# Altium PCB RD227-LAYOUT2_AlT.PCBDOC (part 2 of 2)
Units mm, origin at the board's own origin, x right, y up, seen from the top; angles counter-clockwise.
Board outline 90 x 40 mm, 4 copper layers (TOP, Mid-Layer 1, Mid-Layer 2, BOTTOM), stack 0.711 mm thick; 157 components, 70 nets, 396 pads, 438 vias.
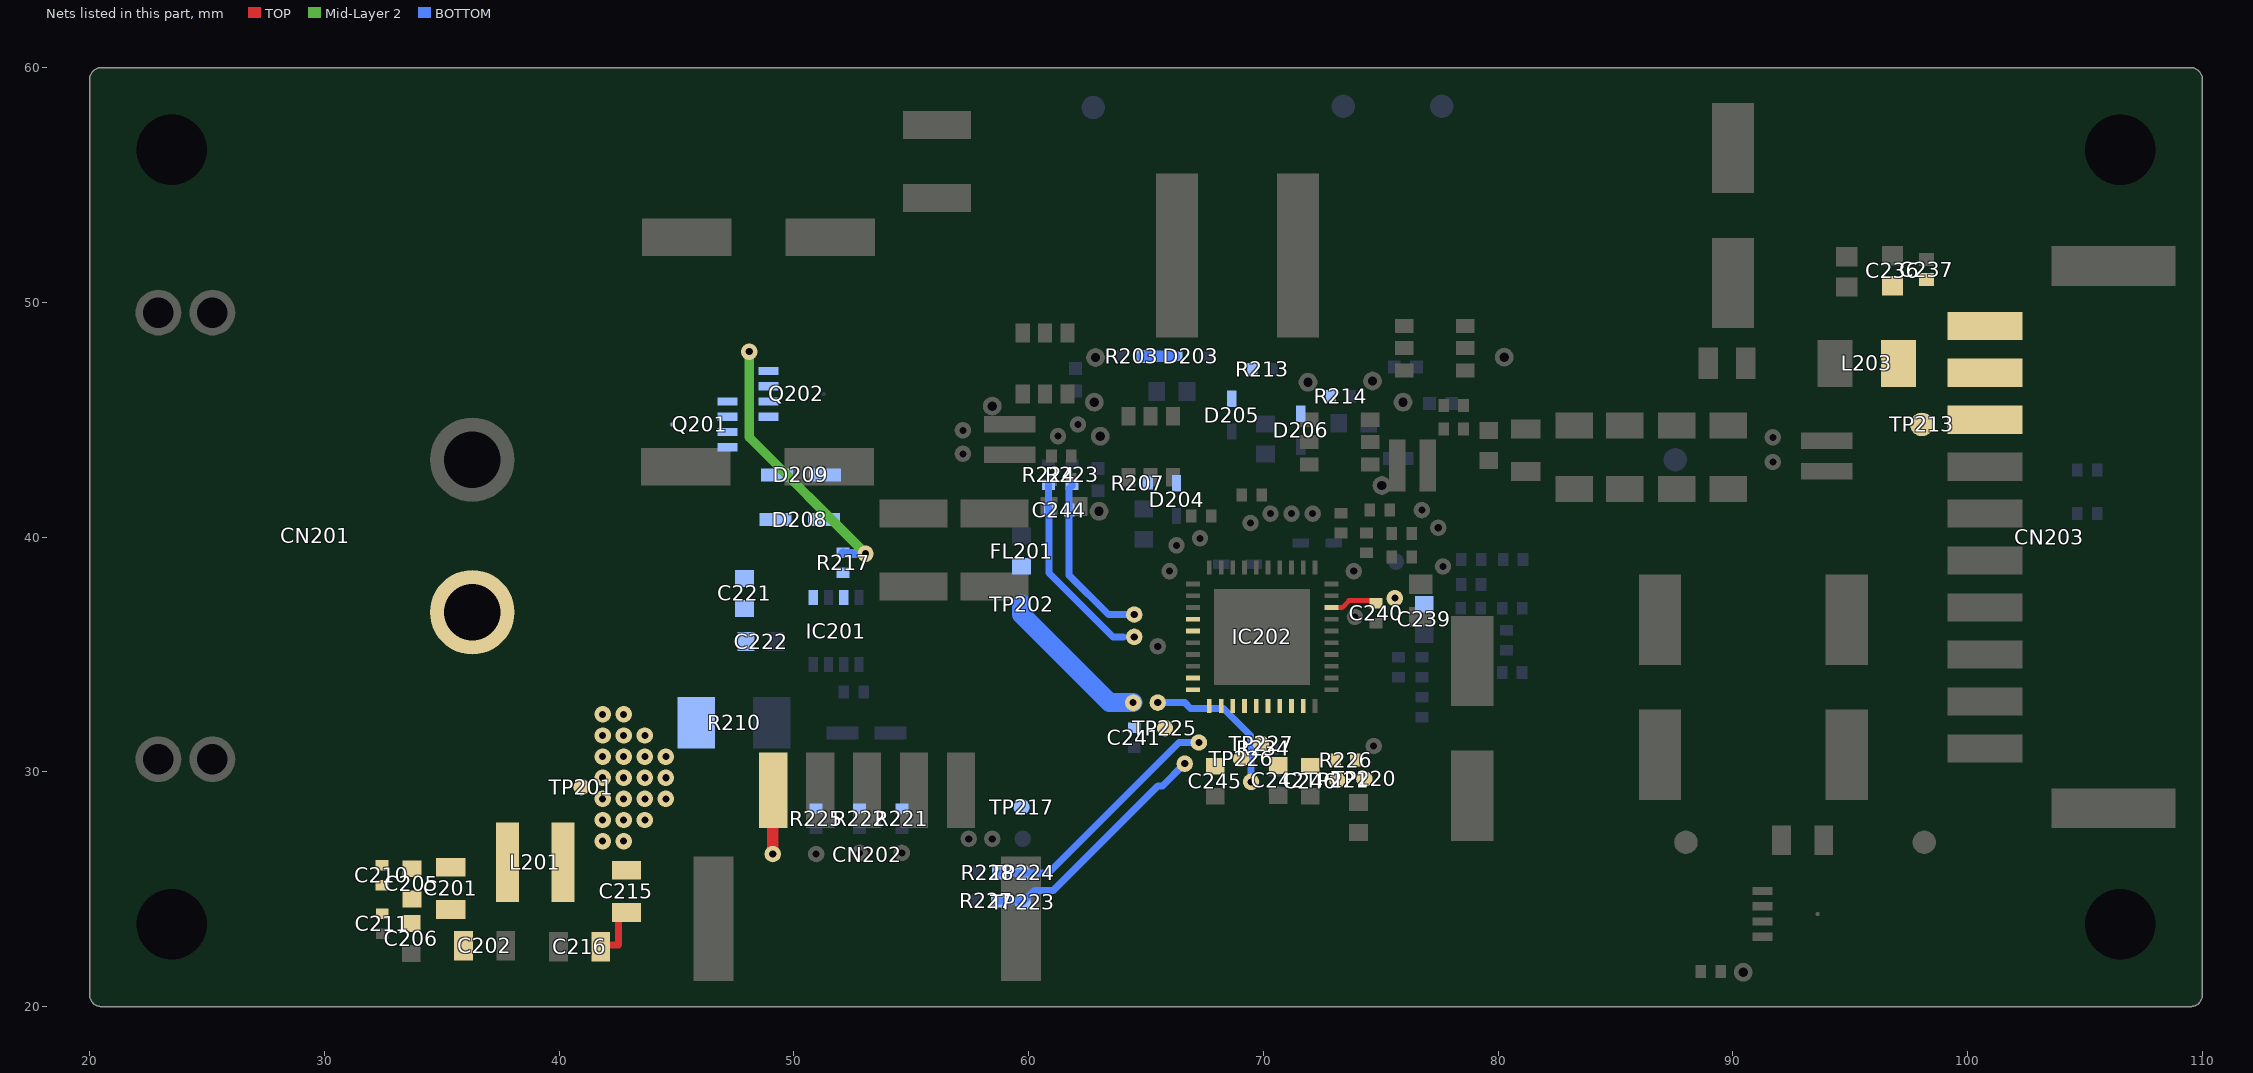
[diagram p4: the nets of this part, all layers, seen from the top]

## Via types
v1: diameter 0.7, hole 0.3, TOP to BOTTOM, 412 vias
v2: diameter 0.8, hole 0.4, TOP to BOTTOM, 26 vias

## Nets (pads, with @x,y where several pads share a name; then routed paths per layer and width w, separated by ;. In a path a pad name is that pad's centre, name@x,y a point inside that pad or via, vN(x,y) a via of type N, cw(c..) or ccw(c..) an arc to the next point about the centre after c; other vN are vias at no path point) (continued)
SIG335: C244.1 IC202.5 pad.@64.5,35.75 R224.1 | length 8.5
  BOTTOM w0.2: 64.05,35.75 pad.@64.5,35.75
  BOTTOM w0.3: R224.1@60.85,42.225 60.85,41.175 C244.1@60.875,41.15 60.875,38.475 63.6,35.75 64.05,35.75
SIG337: C244.2 IC202.4 pad.@64.5,36.7 R223.1 | length 7.4
  BOTTOM w0.3: R223.1@61.85,42.225 61.84,42.235 61.84,42.18 61.725,42.065 C244.2@61.725,41.15 61.725,38.375 63.4,36.7 pad.@64.5,36.7
SIG341: IC202.10 TP225.1
SIG344: IC202.19 R226.1 TP220.1
SIG345: IC202.18 R226.2 TP221.1
SIG346: C245.1 IC202.13
SIG347: C246.1 IC202.17
SIG349: IC202.14 TP226.1
SIG350: IC202.15 TP227.1
SIG369: IC202.11 pad.@66.65,30.35 R227.1 TP223.1 | length 10.4
  BOTTOM w0.3: R227.1@58.675,24.5 59.7,24.5 TP223.1@59.75,24.45 60.25,24.95 61.05,24.95 65.503,29.403 65.703,29.403 pad.@66.65,30.35
SIG370: IC202.12 pad.@67.25,31.25 R228.1 TP224.1 | length 10.9
  BOTTOM w0.3: R228.1@58.675,25.7 TP224.1@59.75,25.7 60.85,25.7 66.4,31.25 pad.@67.25,31.25
SIG395: C201.1 C202.2
SIG396: C205.1 C206.2
SIG397: C210.1 C211.2
SIG411: C215.1 C216.2 | length 2.1
  TOP w0.3: C216.2@41.802,22.63 42.531,22.63 C215.1@42.531,23.955
SIG422: D203.A R203.2 | length 1.3
  BOTTOM w0.5: R203.2@64.875,47.7 D203.A@66.2,47.7
SIG423: D204.A R207.2
SIG424: C221.1 C222.2
SIG425: D205.A R213.2
SIG426: D206.A R214.2
SIG433: IC201.3 R217.1
SIG436: D209.A Q201.1 Q201.2 Q201.3 Q202.1 Q202.2 Q202.3
SIG437: D208.C D209.C
SIG438: D208.A Q201.4 Q202.4 R217.2 | length 11.6
  Mid-Layer 2 w0.4: v1(48.1,47.9) 48.1,44.25 v1(53.05,39.3)
  BOTTOM w0.4: R217.2@52.1,39.325 52.125,39.3 v1(53.05,39.3) v1@53.075,39.3
VBAT: C239.2 C240.2 FL201.2 IC202.28 TP202.1 | length 9
  TOP w0.2: IC202.28@72.898,37 73.35,37 73.65,37.3 C240.2@74.925,37.3
  BOTTOM w0.3: v1(75.6,37.4) v1@75.646,37.446
  BOTTOM w0.8: TP202.1@59.7,37.15 59.7,36.7 63.45,32.95 v1(64.45,32.95)
VBUS: C236.2 C237.2 CN203.8 CN203.9 CN203.10 L203.2 TP213.1
VDD: C241.2 C242.1 CN202.1 IC202.9 IC202.16 pad.@49.1,26.5 pad.@65.5,32.95 pad.@69.475,29.575 R221.1 R222.1 R225.1 R234.1 TP217.1 | length 9.3
  TOP w0.5: pad.@49.1,26.5 CN202.1@49.1,29.2
  BOTTOM w0.3: pad.@65.5,32.95 66.65,32.95 66.9,32.7 68.3,32.7 69.45,31.55 69.45,31.125 R234.1@69.575,31 69.475,30.9 pad.@69.475,29.575
VIN: C201.2 C205.2 C210.2 CN201.1 L201.1
VIN2: C215.2 C221.2 IC201.1 L201.2 Q201.5 R210.2 TP201.1
  other v1: 41.85,27.05 42.75,27.05 41.85,27.95 42.75,27.95 43.65,27.95 41.85,28.85 42.75,28.85 43.65,28.85 44.55,28.85 41.85,29.75 42.75,29.75 43.65,29.75 44.55,29.75 41.85,30.65 42.75,30.65 43.65,30.65 44.55,30.65 41.85,31.55 42.75,31.55 43.65,31.55 41.85,32.45 42.75,32.45
pads on no net: CAM10. CAM11. CAM12. CAM13. IC201.4 IC201.7 IC201.8

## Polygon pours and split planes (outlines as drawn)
CSN2 on TOP "TOP65" (solid, pour order 134): 21 vertices, not listed, extent 89.1,43.8 95.3,52.7
VBUS on TOP "TOP64" (solid, pour order 133): 20 vertices, not listed, extent 96.35,44.221 102.3,51
SHLD_SNS on TOP "TOP63" (solid, pour order 132): 54 vertices, not listed, extent 92.142,20.987 108.927,52.721
CSP2 on TOP "TOP62" (solid, pour order 131): 71.7,41.75 cw(c71.7,41.9) 71.55,41.9 71.55,44.2 cw(c71.7,44.2) 71.7,44.35 75.838,44.35 cw(c75.838,44.2) 75.944,44.306 76.063,44.187 cw(c75.957,44.081) 76.107,44.081 76.107,42.25 cw(c75.957,42.25) 75.957,42.1 75.6,42.1 75.294,41.794 cw(c75.188,41.9) 75.188,41.75
LX2 on TOP "TOP61" (solid, pour order 130): 22 vertices, not listed, extent 70.6,44.7 79,56.35
LX1 on TOP "TOP60" (solid, pour order 129): 25 vertices, not listed, extent 61.35,41.9 67.3,56.45
GND_P on TOP "TOP59" (solid, pour order 128): 215 vertices, not listed, extent 21.05,21 95.65,58.93
DH1_Q on TOP "TOP58" (solid, pour order 127): 62.571,45.4 cw(c62.571,45.45) 62.535,45.415 62.25,45.7 61.65,45.7 cw(c61.65,45.75) 61.6,45.75 61.6,46.45 cw(c61.65,46.45) 61.65,46.5 62.429,46.5 cw(c62.429,46.45) 62.465,46.485 62.835,46.115 cw(c62.8,46.079) 62.85,46.079 62.85,45.45 cw(c62.8,45.45) 62.8,45.4
DL1_Q on TOP "TOP57" (solid, pour order 126): 62.871,44 cw(c62.871,44.05) 62.835,44.015 62.765,44.085 cw(c62.8,44.121) 62.75,44.121 62.75,44.479 cw(c62.8,44.479) 62.765,44.515 63.785,45.535 cw(c63.821,45.5) 63.821,45.55 64.25,45.55 cw(c64.25,45.5) 64.3,45.5 64.3,44.8 cw(c64.25,44.8) 64.25,44.75 64,44.75 63.265,44.015 cw(c63.229,44.05) 63.229,44
DL2_Q on TOP "TOP56" (solid, pour order 125): 75.65,45.7 cw(c75.65,45.75) 75.6,45.75 75.6,47.1 cw(c75.65,47.1) 75.65,47.15 76.35,47.15 cw(c76.35,47.1) 76.4,47.1 76.4,45.871 cw(c76.35,45.871) 76.385,45.835 76.265,45.715 cw(c76.229,45.75) 76.229,45.7
DH2_Q on TOP "TOP55" (solid, pour order 124): 74.2,45.05 cw(c74.2,45.1) 74.15,45.1 74.15,45.929 cw(c74.2,45.929) 74.165,45.965 74.3,46.1 74.3,46.65 cw(c74.35,46.65) 74.35,46.7 74.9,46.7 cw(c74.9,46.65) 74.95,46.65 74.95,45.1 cw(c74.9,45.1) 74.9,45.05
LX2 on TOP "TOP54" (solid, pour order 123): 19 vertices, not listed, extent 68.6,38.4 69.525,43.186
GND_P on TOP "TOP53" (solid, pour order 122): 35 vertices, not listed, extent 78.4,44.2 99.05,59
GND_A on TOP "TOP52" (solid, pour order 121): 77 vertices, not listed, extent 67.55,28.337 77.188,37
SIG344 on TOP "TOP51" (solid, pour order 120): 27 vertices, not listed, extent 71.6,29.7 74.55,33.152
SIG345 on TOP "TOP50" (solid, pour order 119): 20 vertices, not listed, extent 71.1,29.65 73.5,33.152
GDRV on TOP "TOP49" (solid, pour order 118): 89.3,21.1 cw(c89.3,21.15) 89.25,21.15 89.25,21.75 cw(c89.3,21.75) 89.3,21.8 90.2,21.8 90.837,22.437 90.837,23.05 cw(c90.887,23.05) 90.887,23.1 91.65,23.1 cw(c91.65,23.05) 91.7,23.05 91.7,21.721 cw(c91.65,21.721) 91.685,21.685 91.115,21.115 cw(c91.079,21.15) 91.079,21.1
CSP1 on TOP "TOP48" (solid, pour order 117): 23 vertices, not listed, extent 49.65,40.402 61.2,55.1
ADDR on TOP "TOP47" (solid, pour order 116): 70.6,39.2 cw(c70.7,39.2) 70.629,39.271 71.754,40.396 71.754,40.914 cw(c71.854,40.914) 71.854,41.014 72.327,41.014 cw(c72.327,40.914) 72.427,40.914 72.427,40.869 cw(c72.327,40.869) 72.398,40.798 72.2,40.6 cw(c72.1,40.6) 72.171,40.529 70.8,39.159 70.8,38.948 cw(c70.7,38.948) 70.6,38.948
BST2 on TOP "TOP46" (solid, pour order 115): 24 vertices, not listed, extent 69.6,38.8 70.65,41.95
SIG350 on TOP "TOP45" (solid, pour order 114): 69.65,31.2 cw(c69.65,31.3) 69.55,31.3 69.55,31.409 cw(c69.65,31.409) 69.579,31.479 69.6,31.5 69.6,33.052 cw(c69.7,33.052) 69.8,33.052 69.8,31.8 70.146,31.454 cw(c70.075,31.383) 70.175,31.383 70.175,31.316 cw(c70.075,31.316) 70.146,31.245 70.13,31.229 cw(c70.06,31.3) 70.06,31.2
VDD on TOP "TOP44" (solid, pour order 113): 24 vertices, not listed, extent 69.273,29.373 71,33.152
CSN1 on TOP "TOP43" (solid, pour order 112): 58.2,44.6 cw(c58.2,44.75) 58.05,44.75 58.05,48.9 cw(c58.2,48.9) 58.2,49.05 60.85,49.05 cw(c60.85,48.9) 61,48.9 61,46.162 cw(c60.85,46.162) 60.956,46.056 60.3,45.4 60.3,44.75 cw(c60.15,44.75) 60.15,44.6
GND_A on TOP "TOP42" (solid, pour order 111): 108.05,37.1 cw(c108.05,37.15) 108,37.15 108,43.8 cw(c108.05,43.8) 108.05,43.85 108.95,43.85 cw(c108.95,43.8) 109,43.8 109,37.15 cw(c108.95,37.15) 108.95,37.1
SIG397 on TOP "TOP41" (solid, pour order 110): 32.25,23.85 cw(c32.25,23.9) 32.2,23.9 32.2,25.2 cw(c32.25,25.2) 32.25,25.25 32.65,25.25 cw(c32.65,25.2) 32.7,25.2 32.7,23.9 cw(c32.65,23.9) 32.65,23.85
SIG396 on TOP "TOP40" (solid, pour order 109): 33.35,23.45 cw(c33.35,23.5) 33.3,23.5 33.3,24.55 cw(c33.35,24.55) 33.35,24.6 34.05,24.6 cw(c34.05,24.55) 34.1,24.55 34.1,23.5 cw(c34.05,23.5) 34.05,23.45
SIG395 on TOP "TOP39" (solid, pour order 108): 35.6,22 cw(c35.6,22.05) 35.55,22.05 35.55,22.4 34.815,23.135 cw(c34.85,23.171) 34.8,23.171 34.8,24.1 cw(c34.85,24.1) 34.85,24.15 35.95,24.15 cw(c35.95,24.1) 36,24.1 36,23.65 36.285,23.365 cw(c36.25,23.329) 36.3,23.329 36.3,22.05 cw(c36.25,22.05) 36.25,22
VIN2 on TOP "TOP38" (solid, pour order 107): 26 vertices, not listed, extent 39.666,24.507 44.9,33.454
SIG341 on TOP "TOP37" (solid, pour order 106): 24 vertices, not listed, extent 65.65,31.75 67.102,33.6
OUT on TOP "TOP36" (solid, pour order 105): 49 vertices, not listed, extent 76.694,32.75 96.1,45.85
VIN on TOP "TOP35" (solid, pour order 104): 41 vertices, not listed, extent 32.144,24.463 38.304,38.65
GND_A on TOP "TOP34" (solid, pour order 103): 46,21 cw(c46,21.15) 45.85,21.15 45.85,24.65 cw(c46,24.65) 46,24.8 55.45,24.8 56.55,25.9 56.55,30.85 cw(c56.7,30.85) 56.7,31 58.838,31 cw(c58.838,30.85) 58.944,30.956 60.506,29.394 cw(c60.4,29.288) 60.55,29.288 60.55,21.15 cw(c60.4,21.15) 60.4,21
CSN1 on TOP "TOP33" (solid, pour order 102): 61.821,44.65 cw(c61.821,44.7) 61.785,44.665 61.515,44.935 cw(c61.55,44.971) 61.5,44.971 61.5,45.05 cw(c61.55,45.05) 61.55,45.1 62.15,45.1 cw(c62.15,45.05) 62.2,45.05 62.2,44.7 cw(c62.15,44.7) 62.15,44.65
CSP1 on TOP "TOP32" (solid, pour order 101): 60.7,44 cw(c60.7,44.05) 60.65,44.05 60.65,44.179 cw(c60.7,44.179) 60.665,44.215 61.085,44.635 cw(c61.121,44.6) 61.121,44.65 61.25,44.65 cw(c61.25,44.6) 61.3,44.6 61.3,44.05 cw(c61.25,44.05) 61.25,44
LX1 on TOP "TOP31" (solid, pour order 100): 21 vertices, not listed, extent 67.25,38.4 68.3,43.2
ALERT on TOP "TOP30" (solid, pour order 99): 21 vertices, not listed, extent 72.1,31 74.8,32.841
SIG347 on TOP "TOP29" (solid, pour order 98): 71.7,29.9 cw(c71.7,30) 71.6,30 71.6,31.1 70.629,32.071 cw(c70.7,32.141) 70.6,32.141 70.6,33.052 cw(c70.7,33.052) 70.8,33.052 70.8,32.35 72.371,30.779 cw(c72.3,30.709) 72.4,30.709 72.4,30 cw(c72.3,30) 72.3,29.9
SIG349 on TOP "TOP28" (solid, pour order 97): 68.8,30.45 cw(c68.8,30.55) 68.7,30.55 68.7,31.009 cw(c68.8,31.009) 68.729,31.079 69.1,31.45 69.1,33.052 cw(c69.2,33.052) 69.3,33.052 69.3,30.9 69.371,30.829 cw(c69.3,30.759) 69.4,30.759 69.4,30.55 cw(c69.3,30.55) 69.3,30.45
SIG346 on TOP "TOP27" (solid, pour order 96): 67.65,29.9 cw(c67.65,30) 67.55,30 67.55,30.609 cw(c67.65,30.609) 67.579,30.679 67.85,30.95 67.85,31.388 cw(c68,31.388) 67.894,31.494 68.6,32.2 68.6,33.052 cw(c68.7,33.052) 68.8,33.052 68.8,31.591 cw(c68.7,31.591) 68.771,31.521 68.35,31.1 68.35,30 cw(c68.25,30) 68.25,29.9
SIG370 on TOP "TOP26" (solid, pour order 95): 67.129,31.15 cw(c67.129,31.25) 67.029,31.25 67.029,31.409 cw(c67.129,31.409) 67.059,31.479 67.224,31.644 cw(c67.294,31.574) 67.271,31.671 68.1,32.5 68.1,33.052 cw(c68.2,33.052) 68.3,33.052 68.3,32.391 cw(c68.2,32.391) 68.271,32.321 67.6,31.65 67.6,31.25 cw(c67.5,31.25) 67.5,31.15
SIG369 on TOP "TOP25" (solid, pour order 94): 19 vertices, not listed, extent 66.311,30.25 67.8,33.152
HVDP on TOP "TOP24" (solid, pour order 93): 74.45,31.95 cw(c74.45,32.05) 74.35,32.05 74.35,32.959 73.409,33.9 72.898,33.9 cw(c72.898,34) 72.898,34.1 73.45,34.1 cw(c73.45,34) 73.521,34.071 74.827,32.765 cw(c74.756,32.694) 74.856,32.694 74.856,32.452 74.967,32.079 cw(c74.871,32.05) 74.871,31.95
HVDM on TOP "TOP23" (solid, pour order 92): 73.441,32.75 cw(c73.441,32.85) 73.371,32.779 73.329,32.821 cw(c73.4,32.891) 73.3,32.891 73.3,33.259 73.159,33.4 72.898,33.4 cw(c72.898,33.5) 72.898,33.6 73.2,33.6 cw(c73.2,33.5) 73.271,33.571 73.92,32.921 73.921,32.921 cw(c73.85,32.85) 73.95,32.85 cw(c73.85,32.85) 73.85,32.75
HVCC2 on TOP "TOP22" (solid, pour order 91): 74.55,34.1 cw(c74.55,34.2) 74.479,34.129 73.709,34.9 72.898,34.9 cw(c72.898,35) 72.898,35.1 73.75,35.1 cw(c73.75,35) 73.821,35.071 74.342,34.549 cw(c74.35,34.5) 74.35,34.55 74.75,34.55 cw(c74.75,34.5) 74.8,34.5 74.8,34.3 cw(c74.8,34.2) 74.8,34.1
HVCC1 on TOP "TOP21" (solid, pour order 90): 18 vertices, not listed, extent 72.798,34.784 74.8,35.6
VDD on TOP "TOP20" (solid, pour order 89): 20 vertices, not listed, extent 65.3,32.6 67.102,34.1
GDRV on TOP "TOP19" (solid, pour order 88): 65.55,33.65 cw(c65.55,33.7) 65.5,33.7 65.5,34.3 cw(c65.55,34.3) 65.55,34.35 66.309,34.35 66.529,34.571 cw(c66.6,34.5) 66.6,34.6 67.002,34.6 cw(c67.002,34.5) 67.002,34.4 66.641,34.4 66.527,34.286 cw(c66.479,34.3) 66.515,34.265 66.514,34.264 65.915,33.665 cw(c65.879,33.7) 65.879,33.65
HVEN on TOP "TOP18" (solid, pour order 87): 65.45,35.05 cw(c65.45,35.1) 65.4,35.1 65.4,35.65 cw(c65.45,35.65) 65.45,35.7 65.779,35.7 cw(c65.779,35.65) 65.815,35.685 65.9,35.6 67.25,35.6 cw(c67.25,35.55) 67.3,35.55 67.3,35.45 cw(c67.25,35.45) 67.25,35.4 66.1,35.4 65.765,35.065 cw(c65.729,35.1) 65.729,35.05
SIG335 on TOP "TOP17" (solid, pour order 86): 64.25,35.7 cw(c64.25,35.75) 64.2,35.75 64.2,35.979 cw(c64.25,35.979) 64.215,36.015 64.285,36.085 cw(c64.321,36.05) 64.321,36.1 67.25,36.1 cw(c67.25,36.05) 67.3,36.05 67.3,35.95 cw(c67.25,35.95) 67.25,35.9 65,35.9 64.815,35.715 cw(c64.779,35.75) 64.779,35.7
SIG337 on TOP "TOP16" (solid, pour order 85): 64.55,36.4 cw(c64.55,36.45) 64.5,36.45 64.5,36.8 cw(c64.55,36.8) 64.55,36.85 64.729,36.85 cw(c64.729,36.8) 64.765,36.835 65,36.6 67.25,36.6 cw(c67.25,36.55) 67.3,36.55 67.3,36.45 cw(c67.25,36.45) 67.25,36.4
DL1 on TOP "TOP15" (solid, pour order 84): 66.521,37.4 cw(c66.521,37.45) 66.485,37.415 65.665,38.235 cw(c65.7,38.271) 65.65,38.271 65.65,38.5 cw(c65.7,38.5) 65.7,38.55 66.3,38.55 cw(c66.3,38.5) 66.35,38.5 66.35,37.95 66.7,37.6 67.2,37.6 cw(c67.2,37.55) 67.25,37.55 67.25,37.45 cw(c67.2,37.45) 67.2,37.4
BST1 on TOP "TOP14" (solid, pour order 83): 37 vertices, not listed, extent 65.95,37.9 67.2,40.85
DL2 on TOP "TOP13" (solid, pour order 82): 70.15,38.4 cw(c70.15,38.45) 70.1,38.45 70.1,39.529 cw(c70.15,39.529) 70.115,39.565 70.85,40.3 70.85,40.95 cw(c70.9,40.95) 70.9,41 71.5,41 cw(c71.5,40.95) 71.55,40.95 71.55,40.521 cw(c71.5,40.521) 71.535,40.485 70.3,39.25 70.3,38.45 cw(c70.25,38.45) 70.25,38.4
DH2 on TOP "TOP12" (solid, pour order 81): 69.15,38.45 cw(c69.15,38.5) 69.1,38.5 69.1,40.579 cw(c69.15,40.579) 69.115,40.615 69.235,40.735 cw(c69.271,40.7) 69.271,40.75 69.629,40.75 cw(c69.629,40.7) 69.665,40.735 69.785,40.615 cw(c69.75,40.579) 69.8,40.579 69.8,40.371 cw(c69.75,40.371) 69.785,40.335 69.3,39.85 69.3,38.5 cw(c69.25,38.5) 69.25,38.45
VBAT on TOP "TOP11" (solid, pour order 80): 74.621,36.95 cw(c74.621,37) 74.585,36.965 74.365,37.185 cw(c74.4,37.221) 74.35,37.221 74.35,37.35 cw(c74.4,37.35) 74.4,37.4 75.15,37.4 75.235,37.485 cw(c75.271,37.45) 75.271,37.5 75.85,37.5 cw(c75.85,37.45) 75.9,37.45 75.9,37.071 cw(c75.85,37.071) 75.885,37.035 75.815,36.965 cw(c75.779,37) 75.779,36.95
BIAS on TOP "TOP10" (solid, pour order 79): 20 vertices, not listed, extent 74.55,37.6 78,38.85
CSN2 on TOP "TOP9" (solid, pour order 78): 76.15,38.9 cw(c76.15,38.95) 76.1,38.95 76.1,39.4 cw(c76.15,39.4) 76.15,39.45 76.65,39.45 77.1,39.9 77.1,40.45 cw(c77.15,40.45) 77.15,40.5 77.75,40.5 cw(c77.75,40.45) 77.8,40.45 77.8,40.021 cw(c77.75,40.021) 77.785,39.985 76.715,38.915 cw(c76.679,38.95) 76.679,38.9
SIG328 on TOP "TOP8" (solid, pour order 77): 73,40.8 cw(c73,40.85) 72.95,40.85 72.95,41.2 cw(c73,41.2) 73,41.25 73.7,41.25 73.835,41.385 cw(c73.871,41.35) 73.871,41.4 74.6,41.4 cw(c74.6,41.35) 74.65,41.35 74.65,40.95 cw(c74.6,40.95) 74.6,40.9 74.2,40.9 74.115,40.815 cw(c74.079,40.85) 74.079,40.8
SIG324 on TOP "TOP7" (solid, pour order 76): 75.071,38.9 cw(c75.071,38.95) 75.035,38.915 74.85,39.1 74.2,39.1 cw(c74.2,39.15) 74.15,39.15 74.15,39.5 cw(c74.2,39.5) 74.2,39.55 75.079,39.55 cw(c75.079,39.5) 75.115,39.535 75.25,39.4 75.45,39.4 cw(c75.45,39.35) 75.5,39.35 75.5,38.95 cw(c75.45,38.95) 75.45,38.9
SIG310 on TOP "TOP6" (solid, pour order 75): 73.15,36.4 cw(c73.15,36.45) 73.1,36.45 73.1,36.55 cw(c73.15,36.55) 73.15,36.6 73.4,36.6 73.685,36.885 cw(c73.721,36.85) 73.721,36.9 73.9,36.9 cw(c73.9,36.85) 73.95,36.85 73.95,36.45 cw(c73.9,36.45) 73.9,36.4
SIG318 on TOP "TOP5" (solid, pour order 74): 72.75,37.9 cw(c72.75,37.95) 72.7,37.95 72.7,38.05 cw(c72.75,38.05) 72.75,38.1 73,38.1 73.435,38.535 cw(c73.471,38.5) 73.471,38.55 74,38.55 cw(c74,38.5) 74.05,38.5 74.05,38.25 cw(c74,38.25) 74,38.2 73.5,38.2 73.215,37.915 cw(c73.179,37.95) 73.179,37.9
OUT on TOP "TOP4" (solid, pour order 73): 76.15,39.95 cw(c76.15,40) 76.1,40 76.1,40.829 cw(c76.15,40.829) 76.115,40.865 76.385,41.135 cw(c76.421,41.1) 76.421,41.15 77,41.15 cw(c77,41.1) 77.05,41.1 77.05,41.021 cw(c77,41.021) 77.035,40.985 76.55,40.5 76.55,40 cw(c76.5,40) 76.5,39.95
CSP2 on TOP "TOP3" (solid, pour order 72): 75.3,40.9 cw(c75.3,40.95) 75.25,40.95 75.25,41.35 cw(c75.3,41.35) 75.3,41.4 75.65,41.4 75.885,41.635 cw(c75.921,41.6) 75.921,41.65 76.05,41.65 cw(c76.05,41.6) 76.1,41.6 76.1,41.371 cw(c76.05,41.371) 76.085,41.335 75.665,40.915 cw(c75.629,40.95) 75.629,40.9
SIG319 on TOP "TOP2" (solid, pour order 71): 75.271,39.85 cw(c75.271,39.9) 75.235,39.865 75.15,39.95 73.1,39.95 cw(c73.1,40) 73.05,40 73.05,40.35 cw(c73.1,40.35) 73.1,40.4 75.55,40.4 cw(c75.55,40.35) 75.6,40.35 75.6,39.9 cw(c75.55,39.9) 75.55,39.85
DH1 on TOP "TOP1" (solid, pour order 70): 67.65,38.4 cw(c67.65,38.45) 67.6,38.45 67.6,39.2 66.965,39.835 cw(c67,39.871) 66.95,39.871 66.95,40.079 cw(c67,40.079) 66.965,40.115 67.135,40.285 cw(c67.171,40.25) 67.171,40.3 67.429,40.3 cw(c67.429,40.25) 67.465,40.285 67.785,39.965 cw(c67.75,39.929) 67.8,39.929 67.8,38.45 cw(c67.75,38.45) 67.75,38.4
GND_P on Mid-Layer 1 "MID175" (solid, pour order 68): 138 vertices, not listed, extent 20.986,21 101.75,58.981
VIN2 on Mid-Layer 1 "MID168" (solid, pour order 61): 41.5,26.65 cw(c41.5,26.7) 41.45,26.7 41.45,32.85 cw(c41.5,32.85) 41.5,32.9 43.129,32.9 cw(c43.129,32.85) 43.165,32.885 44.935,31.115 cw(c44.9,31.079) 44.95,31.079 44.95,28.321 cw(c44.9,28.321) 44.935,28.285 43.315,26.665 cw(c43.279,26.7) 43.279,26.65
GND_A on Mid-Layer 1 "MID176" (solid, pour order 69): 29 vertices, not listed, extent 68.35,28.424 108.95,44.863
LX1 on Mid-Layer 1 "MID174" (solid, pour order 67): 63.8,43.05 cw(c63.8,43.2) 63.65,43.2 63.65,44.956 cw(c63.8,44.956) 63.8,45.106 66.4,45.106 cw(c66.4,44.956) 66.55,44.956 66.55,43.2 cw(c66.4,43.2) 66.4,43.05
SHLD_SNS on Mid-Layer 1 "MID173" (solid, pour order 66): 18 vertices, not listed, extent 92.2,20.987 106.598,33.739
CSP2 on Mid-Layer 1 "MID172" (solid, pour order 65): 71.9,41.85 cw(c71.9,42) 71.75,42 71.75,43.9 cw(c71.9,43.9) 71.9,44.05 74.15,44.05 cw(c74.15,43.9) 74.3,43.9 74.3,42 cw(c74.15,42) 74.15,41.85
CSN1 on Mid-Layer 1 "MID171" (solid, pour order 64): 59.05,46.5 cw(c59.05,46.65) 58.9,46.65 58.9,48.95 cw(c59.05,48.95) 59.05,49.1 60.9,49.1 cw(c60.9,48.95) 61.05,48.95 61.05,46.65 cw(c60.9,46.65) 60.9,46.5
VBAT on Mid-Layer 1 "MID170" (solid, pour order 63): 28 vertices, not listed, extent 64.05,31.855 75.879,37.523
CSP1 on Mid-Layer 1 "MID169" (solid, pour order 62): 54.271,44.15 cw(c54.271,44.2) 54.235,44.165 53.165,45.235 cw(c53.2,45.271) 53.15,45.271 53.15,50.35 cw(c53.2,50.35) 53.2,50.4 57.4,50.4 cw(c57.4,50.35) 57.45,50.35 57.45,46.171 cw(c57.4,46.171) 57.435,46.135 55.465,44.165 cw(c55.429,44.2) 55.429,44.15
SHLD_SNS on Mid-Layer 1 "MID167" (solid, pour order 60): 92.295,22.65 cw(c92.295,22.75) 92.195,22.75 92.195,24.668 cw(c92.295,24.668) 92.295,24.768 94.144,24.768 cw(c94.144,24.668) 94.244,24.668 94.244,22.75 cw(c94.144,22.75) 94.144,22.65
LX2 on Mid-Layer 1 "MID166" (solid, pour order 59): 76.4,46.95 cw(c76.4,47.1) 76.25,47.1 76.25,49.422 cw(c76.4,49.422) 76.4,49.572 78.1,49.572 cw(c78.1,49.422) 78.25,49.422 78.25,47.1 cw(c78.1,47.1) 78.1,46.95
GND_A on Mid-Layer 2 "MID287" (solid, pour order 58): 40 vertices, not listed, extent 68.35,28.2 108.9,44.863
GND_P on Mid-Layer 2 "MID286" (solid, pour order 57): 174 vertices, not listed, extent 20.95,21.05 101.9,58.864
LX2 on Mid-Layer 2 "MID277" (solid, pour order 48): 76.4,46.95 cw(c76.4,47.1) 76.25,47.1 76.25,49.422 cw(c76.4,49.422) 76.4,49.572 78.1,49.572 cw(c78.1,49.422) 78.25,49.422 78.25,47.1 cw(c78.1,47.1) 78.1,46.95
CSN1 on Mid-Layer 2 "MID281" (solid, pour order 52): 59.05,46.5 cw(c59.05,46.65) 58.9,46.65 58.9,48.9 cw(c59.05,48.9) 59.05,49.05 60.9,49.05 cw(c60.9,48.9) 61.05,48.9 61.05,46.65 cw(c60.9,46.65) 60.9,46.5
CSP1 on Mid-Layer 2 "MID280" (solid, pour order 51): 54.271,44.15 cw(c54.271,44.2) 54.235,44.165 53.165,45.235 cw(c53.2,45.271) 53.15,45.271 53.15,50.35 cw(c53.2,50.35) 53.2,50.4 57.4,50.4 cw(c57.4,50.35) 57.45,50.35 57.45,46.171 cw(c57.4,46.171) 57.435,46.135 55.465,44.165 cw(c55.429,44.2) 55.429,44.15
VIN2 on Mid-Layer 2 "MID279" (solid, pour order 50): 41.5,26.65 cw(c41.5,26.7) 41.45,26.7 41.45,32.85 cw(c41.5,32.85) 41.5,32.9 43.129,32.9 cw(c43.129,32.85) 43.165,32.885 44.935,31.115 cw(c44.9,31.079) 44.95,31.079 44.95,28.321 cw(c44.9,28.321) 44.935,28.285 43.315,26.665 cw(c43.279,26.7) 43.279,26.65
LX1 on Mid-Layer 2 "MID285" (solid, pour order 56): 63.8,43.05 cw(c63.8,43.2) 63.65,43.2 63.65,44.956 cw(c63.8,44.956) 63.8,45.106 66.4,45.106 cw(c66.4,44.956) 66.55,44.956 66.55,43.2 cw(c66.4,43.2) 66.4,43.05
SHLD_SNS on Mid-Layer 2 "MID284" (solid, pour order 55): 18 vertices, not listed, extent 92.2,20.987 106.692,33.954
GND_P on Mid-Layer 2 "MID283" (solid, pour order 54): 17 vertices, not listed, extent 79.9,28.2 93.7,29.45
CSP2 on Mid-Layer 2 "MID282" (solid, pour order 53): 71.75,41.914 cw(c71.75,42.064) 71.6,42.064 71.6,43.75 cw(c71.75,43.75) 71.75,43.9 73.985,43.9 cw(c73.985,43.75) 74.135,43.75 74.135,42.064 cw(c73.985,42.064) 73.985,41.914
GND_P on Mid-Layer 2 "MID278" (solid, pour order 49): 68.094,33.7 cw(c68.094,33.85) 67.944,33.85 67.944,37.65 cw(c68.094,37.65) 68.094,37.8 71.852,37.8 cw(c71.852,37.65) 72.002,37.65 72.002,33.85 cw(c71.852,33.85) 71.852,33.7
SIG437 on BOTTOM "BOTTOM133" (solid, pour order 47): 25 vertices, not listed, extent 48.6,40.45 52,42.9
VIN2 on BOTTOM "BOTTOM132" (solid, pour order 46): 31 vertices, not listed, extent 40.726,26.7 51,46.074
CSP1 on BOTTOM "BOTTOM131" (solid, pour order 45): 49.9,43.725 cw(c49.9,43.775) 49.85,43.775 49.85,49.679 cw(c49.9,49.679) 49.865,49.715 50.485,50.335 cw(c50.521,50.3) 50.521,50.35 57.3,50.35 cw(c57.3,50.2) 57.45,50.2 57.45,46.212 cw(c57.3,46.212) 57.406,46.106 56.057,44.757 56.057,44.728 cw(c56.007,44.728) 56.042,44.692 55.09,43.74 cw(c55.054,43.775) 55.054,43.725
SIG433 on BOTTOM "BOTTOM130" (solid, pour order 44): 52,37.35 cw(c52,37.4) 51.95,37.4 51.95,37.95 51.815,38.085 cw(c51.85,38.121) 51.8,38.121 51.8,38.65 cw(c51.85,38.65) 51.85,38.7 52.35,38.7 cw(c52.35,38.65) 52.4,38.65 52.4,38.071 cw(c52.35,38.071) 52.385,38.035 52.3,37.95 52.3,37.4 cw(c52.25,37.4) 52.25,37.35
SIG438 on BOTTOM "BOTTOM129" (solid, pour order 43): 19 vertices, not listed, extent 50.6,39.25 52.4,41
SIG438 on BOTTOM "BOTTOM128" (solid, pour order 42): 20 vertices, not listed, extent 46.75,39.1 52.35,44
SIG436 on BOTTOM "BOTTOM127" (solid, pour order 41): 17 vertices, not listed, extent 46.75,42.35 49.95,46.6
SIG438 on BOTTOM "BOTTOM126" (solid, pour order 40): 17 vertices, not listed, extent 47.75,46.9 49.15,48.25
LX1 on BOTTOM "BOTTOM125" (solid, pour order 39): 64.6,43.05 cw(c64.6,43.2) 64.45,43.2 64.45,44.956 cw(c64.6,44.956) 64.6,45.106 66.4,45.106 cw(c66.4,44.956) 66.55,44.956 66.55,43.2 cw(c66.4,43.2) 66.4,43.05
GND_P on BOTTOM "BOTTOM124" (solid, pour order 38): 29 vertices, not listed, extent 49,31.2 58.45,38.2
GND_A on BOTTOM "BOTTOM123" (solid, pour order 37): 36 vertices, not listed, extent 56.8,26.75 70.8,32.25
BIAS on BOTTOM "BOTTOM122" (solid, pour order 36): 34 vertices, not listed, extent 69.423,38.4 78.6,39.95
SHLD_SNS on BOTTOM "BOTTOM121" (solid, pour order 35): 18 vertices, not listed, extent 92.2,20.987 106.682,33.886
GND_P on BOTTOM "BOTTOM120" (solid, pour order 34): 151 vertices, not listed, extent 20.95,21 102.5,58.95
LX1 on BOTTOM "BOTTOM119" (solid, pour order 33): 61.95,46.9 cw(c61.95,46.95) 61.9,46.95 61.9,47.429 cw(c61.95,47.429) 61.915,47.465 62.435,47.985 cw(c62.471,47.95) 62.471,48 62.9,48 cw(c62.9,47.95) 62.95,47.95 62.95,47.35 cw(c62.9,47.35) 62.9,47.3 62.75,47.3 62.365,46.915 cw(c62.329,46.95) 62.329,46.9
DH1_Q on BOTTOM "BOTTOM118" (solid, pour order 32): 26 vertices, not listed, extent 61.85,45.4 65.709,47.949
SIG423 on BOTTOM "BOTTOM117" (solid, pour order 31): 65,42.05 cw(c65,42.1) 64.95,42.1 64.95,42.5 cw(c65,42.5) 65,42.55 66.3,42.55 cw(c66.3,42.5) 66.35,42.5 66.35,42.1 cw(c66.3,42.1) 66.3,42.05
GND_P on BOTTOM "BOTTOM116" (solid, pour order 30): 24 vertices, not listed, extent 62.4,33.7 68.85,42
DL1_Q on BOTTOM "BOTTOM115" (solid, pour order 29): 24 vertices, not listed, extent 62.7,40.9 65.3,44.35
DL1 on BOTTOM "BOTTOM114" (solid, pour order 28): 20 vertices, not listed, extent 64.5,38.2 66.5,41.15
SIG426 on BOTTOM "BOTTOM113" (solid, pour order 27): 71.45,44.9 cw(c71.45,44.95) 71.4,44.95 71.4,45.55 cw(c71.45,45.55) 71.45,45.6 71.9,45.6 72.535,46.235 cw(c72.571,46.2) 72.571,46.25 73,46.25 cw(c73,46.2) 73.05,46.2 73.05,45.8 cw(c73,45.8) 73,45.75 72.7,45.75 71.865,44.915 cw(c71.829,44.95) 71.829,44.9
DH2_Q on BOTTOM "BOTTOM112" (solid, pour order 26): 35 vertices, not listed, extent 69.65,44.448 75.55,47.8
DL2_Q on BOTTOM "BOTTOM111" (solid, pour order 25): 22 vertices, not listed, extent 73.5,44.45 77.1,46.25
CSP2 on BOTTOM "BOTTOM110" (solid, pour order 24): 72.6,41.85 cw(c72.6,42) 72.45,42 72.45,43.429 cw(c72.5,43.429) 72.465,43.465 73.035,44.035 cw(c73.071,44) 73.071,44.05 75.35,44.05 cw(c75.35,43.9) 75.5,43.9 75.5,42 cw(c75.35,42) 75.35,41.85
DL2 on BOTTOM "BOTTOM109" (solid, pour order 23): 22 vertices, not listed, extent 70.85,41 73.3,45.25
SIG425 on BOTTOM "BOTTOM108" (solid, pour order 22): 68.5,45.6 cw(c68.5,45.65) 68.45,45.65 68.45,46.529 cw(c68.5,46.529) 68.465,46.565 69.285,47.385 cw(c69.321,47.35) 69.321,47.4 69.7,47.4 cw(c69.7,47.35) 69.75,47.35 69.75,46.921 cw(c69.7,46.921) 69.735,46.885 68.85,46 68.85,45.65 cw(c68.8,45.65) 68.8,45.6
VBAT on BOTTOM "BOTTOM107" (solid, pour order 21): 59.3,38.62 cw(c59.7,38.62) 59.7,39.02 cw(c59.7,38.62) 60.1,38.62 60.1,37.15 cw(c59.7,37.15) 59.3,37.15
CSP1 on BOTTOM "BOTTOM106" (solid, pour order 20): 59.7,39.74 cw(c59.7,40.14) 59.3,40.14 59.3,40.884 56.917,43.267 cw(c57.2,43.55) 57.483,43.833 59.983,41.333 cw(c59.7,41.05) 60.1,41.05 60.1,40.14 cw(c59.7,40.14) 59.7,39.74
CSN1 on BOTTOM "BOTTOM105" (solid, pour order 19): 59.05,46.5 cw(c59.05,46.65) 58.9,46.65 58.9,48.9 cw(c59.05,48.9) 59.05,49.05 60.9,49.05 cw(c60.9,48.9) 61.05,48.9 61.05,46.65 cw(c60.9,46.65) 60.9,46.5
GND_A on BOTTOM "BOTTOM104" (solid, pour order 18): 29 vertices, not listed, extent 105.526,36.396 108.9,44.272
SIG247 on BOTTOM "BOTTOM103" (solid, pour order 17): 22 vertices, not listed, extent 48.95,31 52.75,34.65
SIG424 on BOTTOM "BOTTOM102" (solid, pour order 16): 47.65,35.15 cw(c47.65,35.2) 47.6,35.2 47.6,36.2 47.515,36.285 cw(c47.55,36.321) 47.5,36.321 47.5,36.9 cw(c47.55,36.9) 47.55,36.95 48.25,36.95 cw(c48.25,36.9) 48.3,36.9 48.3,35.2 cw(c48.25,35.2) 48.25,35.15
GND_P on BOTTOM "BOTTOM101" (solid, pour order 15): 48.242,21 cw(c48.242,21.15) 48.092,21.15 48.092,22.15 cw(c48.242,22.15) 48.242,22.3 64.6,22.3 cw(c64.6,22.15) 64.75,22.15 64.75,21.15 cw(c64.6,21.15) 64.6,21
GND_A on BOTTOM "BOTTOM100" (solid, pour order 14): 53 vertices, not listed, extent 72.15,28.25 82.65,39.318
VDD on BOTTOM "BOTTOM99" (solid, pour order 13): 41 vertices, not listed, extent 48.75,26.255 65.85,32.95
GND_P on BOTTOM "BOTTOM98" (solid, pour order 12): 68.094,33.7 cw(c68.094,33.85) 67.944,33.85 67.944,37.65 cw(c68.094,37.65) 68.094,37.8 71.852,37.8 cw(c71.852,37.65) 72.002,37.65 72.002,33.85 cw(c71.852,33.85) 71.852,33.7
SIG317 on BOTTOM "BOTTOM97" (solid, pour order 11): 22 vertices, not listed, extent 78.964,34.95 80.454,36.25
ADDR on BOTTOM "BOTTOM96" (solid, pour order 10): 79.2,38.8 cw(c79.2,38.95) 79.05,38.95 79.05,39.472 cw(c79.194,39.516) 79.322,39.593 79.615,39.3 80.3,39.3 cw(c80.3,39.15) 80.45,39.15 80.45,38.95 cw(c80.3,38.95) 80.3,38.8
ADDR on BOTTOM "BOTTOM95" (solid, pour order 9): 40 vertices, not listed, extent 72.008,39.4 79.328,41.342
OUT on BOTTOM "BOTTOM94" (solid, pour order 8): 76.771,40.8 cw(c76.771,40.85) 76.735,40.815 76.715,40.835 cw(c76.75,40.871) 76.7,40.871 76.7,41.45 cw(c76.75,41.45) 76.75,41.5 77.029,41.5 cw(c77.029,41.45) 77.065,41.485 77.1,41.45 77.2,41.45 cw(c77.2,41.4) 77.25,41.4 77.25,41.221 cw(c77.2,41.221) 77.235,41.185 76.865,40.815 cw(c76.829,40.85) 76.829,40.8
BST2 on BOTTOM "BOTTOM93" (solid, pour order 7): 18 vertices, not listed, extent 69.95,39.55 71.85,41
DH2 on BOTTOM "BOTTOM92" (solid, pour order 6): 23 vertices, not listed, extent 68.55,40.5 70.477,44.745
SIG425 on BOTTOM "BOTTOM91" (solid, pour order 5): 68.856,46.091 cw(c68.856,46.341) 68.68,46.518 68.933,46.771 cw(c69.109,46.594) 69.109,46.844 cw(c69.109,46.594) 69.286,46.417 69.033,46.164 cw(c68.856,46.341) 68.856,46.091
BST1 on BOTTOM "BOTTOM90" (solid, pour order 4): 17 vertices, not listed, extent 66.3,38.65 68.25,39.9
VBAT on BOTTOM "BOTTOM89" (solid, pour order 3): 76.271,36.8 cw(c76.271,36.85) 76.235,36.815 75.95,37.1 75.6,37.1 cw(c75.6,37.15) 75.55,37.15 75.55,37.7 cw(c75.6,37.7) 75.6,37.75 76.329,37.75 cw(c76.329,37.7) 76.365,37.735 76.6,37.5 77.05,37.5 cw(c77.05,37.45) 77.1,37.45 77.1,36.85 cw(c77.05,36.85) 77.05,36.8
LX2 on BOTTOM "BOTTOM88" (solid, pour order 2): 76.4,46.95 cw(c76.4,47.1) 76.25,47.1 76.25,49.422 cw(c76.4,49.422) 76.4,49.572 78.1,49.572 cw(c78.1,49.422) 78.25,49.422 78.25,47.1 cw(c78.1,47.1) 78.1,46.95
no net on Top Solder "TOPSOLDER139" (solid, pour order 0): 58.6,45.35 58.6,45.15 58.3,45.15 58.3,45.35
no net on Top Solder "TOPSOLDER138" (solid, pour order 0): 75.65,42.15 cw(c75.5,42.15) 75.5,42 75.1,42 cw(c75.1,42.15) 74.95,42.15 74.95,42.3 cw(c75.1,42.3) 75.1,42.45 75.5,42.45 cw(c75.5,42.3) 75.65,42.3
no net on Top Solder "TOPSOLDER137" (solid, pour order 0): 104.5,56.5 ccw(c106.5,56.5) 108.5,56.5 ccw(c106.5,56.5)
no net on Top Solder "TOPSOLDER136" (solid, pour order 0): 104.5,23.5 ccw(c106.5,23.5) 108.5,23.5 ccw(c106.5,23.5)
no net on Top Solder "TOPSOLDER135" (solid, pour order 0): 21.5,23.5 ccw(c23.5,23.5) 25.5,23.5 ccw(c23.5,23.5)
no net on Top Solder "TOPSOLDER134" (solid, pour order 0): 21.5,56.5 ccw(c23.5,56.5) 25.5,56.5 ccw(c23.5,56.5)
no net on Bottom Solder "BOTTOMSOLDER143" (solid, pour order 0): 21.5,23.5 ccw(c23.5,23.5) 25.5,23.5 ccw(c23.5,23.5)
no net on Bottom Solder "BOTTOMSOLDER142" (solid, pour order 0): 21.5,56.5 ccw(c23.5,56.5) 25.5,56.5 ccw(c23.5,56.5)
no net on Bottom Solder "BOTTOMSOLDER141" (solid, pour order 0): 104.5,23.5 ccw(c106.5,23.5) 108.5,23.5 ccw(c106.5,23.5)
no net on Bottom Solder "BOTTOMSOLDER140" (solid, pour order 0): 104.5,56.5 ccw(c106.5,56.5) 108.5,56.5 ccw(c106.5,56.5)
no net on Top Overlay "TOPOVERLAY151" (solid, pour order 0): 45 vertices, not listed, extent 29.958,54.945 32.085,57.268
no net on Top Overlay "TOPOVERLAY150" (solid, pour order 0): 55 vertices, not listed, extent 38.597,54.985 40.532,57.231
no net on Top Overlay "TOPOVERLAY149" (solid, pour order 0): 34.833,57.232 35.467,57.232 35.467,56.411 36.204,56.411 36.204,57.232 36.838,57.232 36.838,54.982 36.204,54.982 36.204,55.848 35.467,55.848 35.467,54.982 34.833,54.982
no net on Top Overlay "TOPOVERLAY148" (solid, pour order 0): 32 vertices, not listed, extent 40.702,54.982 42.998,57.232
no net on Top Overlay "TOPOVERLAY147" (solid, pour order 0): 127 vertices, not listed, extent 32.454,54.947 34.413,57.268
no net on Top Overlay "TOPOVERLAY146" (solid, pour order 0): 27.728,57.232 29.738,57.232 29.738,56.67 29.072,56.67 29.069,54.985 28.4,54.982 28.4,56.67 27.728,56.67
no net on Top Overlay "TOPOVERLAY145" (solid, pour order 0): 37.397,57.224 cw(c37.403,57.222) 37.403,57.229 37.465,57.23 37.555,57.232 37.717,57.232 38.034,57.232 38.034,54.982 37.397,54.985 37.395,56.101 37.395,56.529 37.395,56.891 37.395,57.217 cw(c37.415,57.217) 37.397,57.224
no net on Top Overlay "TOPOVERLAY144" (solid, pour order 0): 47.55,35.8 cw(c47.75,35.8) 47.75,36 51.65,36 cw(c51.65,35.8) 51.85,35.8 51.85,33.5 cw(c51.65,33.5) 51.65,33.3 47.75,33.3 cw(c47.75,33.5) 47.55,33.5

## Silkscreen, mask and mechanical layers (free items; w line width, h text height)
Top Overlay:
  lines w0.2: 58.5,37 60.9,37 60.9,36.845 60.9,37.7 61.5,38.3 61.5,40.6 ; 60.9,36.9 60.9,37.2 ; 61.3,36.717 61.3,37 64,37 ; 64,36.8 64,37 ; 64,37.6 64,37 ; 64,37.801 64,37.9 64.063,37.963 ; 64.287,38.187 65.5,39.4 65.5,39.9 65.9,40.3 ; 64.6,40.7 64.6,40.3 67.042,40.3 ; 65.4,29.6 66.7,29.6 67.1,30 67.1,30.7 67.216,30.816 ; 65.4,30.7 65.7,30.7 66,31 66.9,31.9 68.8,31.9 69.1,31.6 69.3,31.6 ; 67.558,40.3 68.2,40.3 69,41.1 ; 67.606,31 68.6,31 ; 72.8,25.5 72.8,25.8 72.9,25.9 ; 72.9,28.1 72.9,25.9 ; 76.41,24.49 75.7,25.2 75.7,25.9 72.9,25.9 ; 76.489,24.411 76.5,24.4 ; 76.6,55.5 76.6,52.3 77,52.3 ; 76.728,39.7 77,39.7 ; 76.8,52.3 85.5,52.3 ; 77.1,40.142 77.1,39.1 77.259,38.941 ; 77.1,40.658 77.1,40.892 ; 77.179,41.079 77.4,41.3 78.8,41.3 78.8,41.9 ; 77.6,38.318 77.6,37.3 77.69,37.21 ; 79.1,46.2 79.3,46 79.3,45.6 81.079,45.6 ; 81.421,45.6 81.979,45.6 ; 82.321,45.6 82.879,45.6 ; 83.221,45.6 83.779,45.6 ; 84.121,45.6 84.679,45.6 ; 84.4,45.7 84.4,46.1 ; 84.4,46 84.4,52.3 ; 85.021,45.6 85.579,45.6 ; 85.921,45.6 86.479,45.6 ; 86.821,45.6 87.379,45.6 ; 87.721,45.6 88.6,45.6 ; 89.5,22.5 90.13,21.87
  text "OUTPUT" at 99.8,52.45 h0.71
  text "INPUT" at 21.45,51.435 h0.8
  text "BUCK-BOOST" at 40.195,36.398 h0.89
  text "TYPE2" at 40.2,34.45 h0.71
  text "CONTROL" at 61.201,24.206 h0.8
  text "INPUT" at 61.201,22.796 h0.8
Bottom Overlay:
  lines w0.2: 50.9,51.75 50.9,50.85 53.85,50.85 ; 53.3,50.85 58,50.85 ; 58.125,45.975 57.95,46.15 57.95,46.55 57.95,50.85 58.45,50.85 58.45,51.85 ; 59.15,50.1 59.15,49.7 65.65,49.7 65.65,50.2 ; 60.85,46.71 60.85,45.75 60.85,45.25 61.387,44.713 ; 60.85,47.19 60.85,47.61 ; 60.85,48.09 60.85,49.7 ; 61.4,46.75 61.4,48.9 63.6,48.9 ; 61.663,44.437 62.35,43.75 62.35,43.412 ; 62.35,42.562 62.35,42.738 ; 62.45,43.6 63.25,43.6 63.9,42.95 65.199,42.95 ; 63.4,48.9 66.6,48.9 66.6,55.5 65.7,55.5 ; 64.8,54.1 65.6,54.1 65.6,57 64.8,57 ; 65.4,42.95 65.75,42.95 ; 66.7,48.9 68.7,48.9 68.7,48.6 ; 68,53 68,52.2 69.8,52.2 ; 68.9,46.7 68.9,47.8 70.9,47.8 70.9,47.1 ; 69.85,47.85 69.85,52.2 71.1,52.2 71.1,53 ; 71.25,46 71.25,47.4 73.9,47.4 73.9,46.9 73.9,46.75 74.169,46.481 ; 72.1,52.597 72.1,52.2 75.3,52.2 75.3,52.7 75.3,53 ; 73.7,47.4 73.7,49.85 ; 73.7,49.8 73.7,52.2 ; 74.481,46.169 75.25,45.4 75.25,45 ; 75.1,30.929 75.1,26.8 78.8,26.8 ; 75.1,31.271 75.1,31.7 ; 75.135,31.1 77.4,31.1 77.4,32.1 ; 76.85,51.05 76.85,50.25 81.75,50.25 81.75,51.7 ; 77.8,33.6 77.8,33.2 ; 77.8,38.3 77.9,38.3 ; 77.8,39.3 77.8,39.7 81.7,39.7 81.7,39.2 81.7,38.3 81.1,38.3 ; 78.8,28.1 77.8,28.1 77.8,33.2 ; 80,38.3 81,38.3 ; 80.25,48.18 80.25,50.15 ; 81.7,33.8 81.7,33.2 77.8,33.2 ; 81.7,39.5 81.7,39.9 ; 81.7,39.8 81.7,40.6 ; 82.2,34.7 81.8,35.1 ; 82.2,35.5 81.8,35.1 ; 83,35.1 81.8,35.1 ; 84,29.9 83.1,29.9 83.1,39.3 83.8,39.3 91,39.3
  text "ADDR SELECT" at 84.9,40.7 h0.43
  text "VOLTAGE COMP" at 85.885,26.1 h0.43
